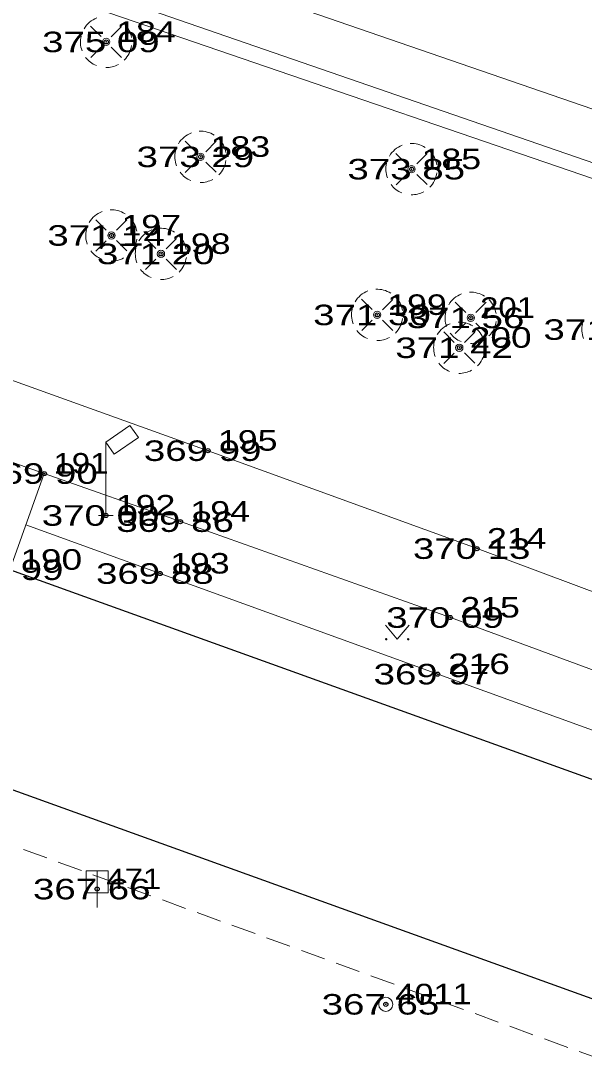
# Model space of a CAD drawing. Extents: x -789669 to -789458, y -977587 to -977420.
# Drawn here: x -789569.11 to -789549.89, y -977497.54 to -977462.39 of the extents above; entities that cross this region are included whole.
import ezdxf
from ezdxf.enums import TextEntityAlignment as Align

# ---------------------------------------------------------------- set-up
doc = ezdxf.new("R2010")
doc.units = 0
doc.header["$LTSCALE"] = 0.28
doc.header["$PDMODE"] = 32
doc.header["$PDSIZE"] = 0.14
doc.linetypes.add('MEDIUM_DASHED', pattern=[4.5, 3, -1.5])
for name, color, linetype, lineweight in [('1', 7, 'Continuous', 13), ('25', 7, 'Continuous', 13), ('3', 7, 'Continuous', 13), ('33', 7, 'Continuous', 13), ('4', 7, 'Continuous', 13), ('50', 7, 'Continuous', 13), ('9', 7, 'Continuous', 25)]:
    doc.layers.add(name, color=color, linetype=linetype, lineweight=lineweight)
for name, color, linetype in [('57', 7, 'Continuous'), ('58', 7, 'Continuous'), ('59', 7, 'Continuous')]:
    doc.layers.add(name, color=color, linetype=linetype)

msp = doc.modelspace()

# ---------------------------------------------------------------- linework, layer by layer
at = {"layer": '1'}
for p, q in [((-789568.3, -977477.84), (-789569.47, -977481.12)), ((-789542.996, -977488.992), (-789568.925, -977479.592))]:
    msp.add_line(p, q, dxfattribs=at)
for points in [[(-789509.64, -977479.12), (-789526.32, -977473.4), (-789544.78, -977467.07), (-789566.2, -977459.68), (-789586.28, -977452.77), (-789604.78, -977446.41), (-789630.61, -977437.53), (-789654.9, -977429.37)], [(-789604.26, -977448.38), (-789586.79, -977454.41), (-789566.59, -977461.37), (-789545.35, -977468.71), (-789526.33, -977475.15), (-789510.21, -977480.66), (-789489.34, -977487.73), (-789463.94, -977496.44)], [(-789591.43, -977469.4), (-789579.77, -977473.66), (-789573.29, -977476.09), (-789568.3, -977477.84), (-789563.66, -977479.48), (-789554.46, -977482.75), (-789542.34, -977487.22), (-789543.54, -977490.46)], [(-789528.28, -977489.67), (-789537.88, -977485.96), (-789544.73, -977483.69), (-789553.55, -977480.4), (-789562.72, -977477.06), (-789579.25, -977471.12)]]:
    msp.add_lwpolyline(points, dxfattribs=at)
at = {"layer": '25'}
msp.add_lwpolyline([(-789566.5, -977492.635), (-789566.5, -977491.385), (-789566.125, -977491.385), (-789566.125, -977492.135), (-789566.875, -977492.135), (-789566.875, -977491.385), (-789566.5, -977491.385)], dxfattribs=at)
at = {"layer": '3'}
msp.add_lwpolyline([(-789601.84, -977457.06), (-789598.55, -977450.95), (-789566.5, -977461.99), (-789545.47, -977469.2), (-789526.54, -977475.63), (-789520.95, -977477.5)], dxfattribs=at)
at = {"layer": '33'}
for p, q in [((-789566.2, -977476.77), (-789566.2, -977479.27)), ((-789566.45, -977479.27), (-789565.95, -977479.27))]:
    msp.add_line(p, q, dxfattribs=at)
msp.add_lwpolyline([(-789566.2, -977476.77), (-789565.38, -977476.197), (-789565.094, -977476.607), (-789565.914, -977477.18)], close=True, dxfattribs=at)
at = {"layer": '4'}
for p, q in [((-789566.724, -977462.582), (-789566.367, -977462.938)), ((-789565.664, -977462.59), (-789566.017, -977462.943)), ((-789566.72, -977463.653), (-789566.368, -977463.302)), ((-789566.19, -977463.126), (-789566.19, -977463.114)), ((-789566.016, -977463.297), (-789565.664, -977463.647)), ((-789563.504, -977466.502), (-789563.147, -977466.858)), ((-789562.444, -977466.51), (-789562.797, -977466.863)), ((-789563.5, -977467.573), (-789563.148, -977467.222)), ((-789562.97, -977467.046), (-789562.97, -977467.034)), ((-789562.796, -977467.217), (-789562.444, -977467.567)), ((-789556.314, -977466.922), (-789555.957, -977467.278)), ((-789555.254, -977466.93), (-789555.607, -977467.283)), ((-789555.78, -977467.466), (-789555.78, -977467.454)), ((-789556.31, -977467.993), (-789555.958, -977467.642)), ((-789555.606, -977467.637), (-789555.254, -977467.987)), ((-789566.544, -977469.182), (-789566.187, -977469.538)), ((-789565.484, -977469.19), (-789565.837, -977469.543)), ((-789566.01, -977469.726), (-789566.01, -977469.714)), ((-789566.54, -977470.253), (-789566.188, -977469.902)), ((-789565.836, -977469.897), (-789565.484, -977470.247)), ((-789564.854, -977469.812), (-789564.497, -977470.168)), ((-789563.794, -977469.82), (-789564.147, -977470.173)), ((-789564.32, -977470.356), (-789564.32, -977470.344)), ((-789564.85, -977470.883), (-789564.498, -977470.532)), ((-789564.146, -977470.527), (-789563.794, -977470.877)), ((-789557.484, -977471.892), (-789557.127, -977472.248)), ((-789556.424, -977471.9), (-789556.777, -977472.253)), ((-789554.294, -977471.992), (-789553.937, -977472.348)), ((-789553.234, -977472), (-789553.587, -977472.353)), ((-789556.95, -977472.436), (-789556.95, -977472.424)), ((-789553.76, -977472.536), (-789553.76, -977472.524)), ((-789557.48, -977472.963), (-789557.128, -977472.612)), ((-789556.776, -977472.607), (-789556.424, -977472.957)), ((-789554.29, -977473.063), (-789553.938, -977472.712)), ((-789553.586, -977472.707), (-789553.234, -977473.057)), ((-789554.684, -977473.012), (-789554.327, -977473.368)), ((-789553.624, -977473.02), (-789553.977, -977473.373)), ((-789554.15, -977473.556), (-789554.15, -977473.544)), ((-789554.68, -977474.083), (-789554.328, -977473.732)), ((-789553.976, -977473.727), (-789553.624, -977474.077))]:
    msp.add_line(p, q, dxfattribs=at)
for points in [[(-789556.672, -977483.011), (-789556.27, -977483.49), (-789555.868, -977483.011)], [(-789556.644, -977483.467), (-789556.63, -977483.475), (-789556.625, -977483.49), (-789556.631, -977483.503), (-789556.644, -977483.511), (-789556.66, -977483.503), (-789556.666, -977483.49), (-789556.662, -977483.476), (-789556.651, -977483.47), (-789556.636, -977483.476), (-789556.631, -977483.49), (-789556.634, -977483.5), (-789556.644, -977483.505), (-789556.655, -977483.5), (-789556.661, -977483.489), (-789556.656, -977483.479), (-789556.651, -977483.476), (-789556.64, -977483.48), (-789556.635, -977483.49), (-789556.641, -977483.497), (-789556.649, -977483.495), (-789556.654, -977483.487), (-789556.649, -977483.482), (-789556.641, -977483.486), (-789556.644, -977483.49)], [(-789555.894, -977483.468), (-789555.88, -977483.476), (-789555.875, -977483.491), (-789555.881, -977483.504), (-789555.894, -977483.512), (-789555.91, -977483.504), (-789555.916, -977483.491), (-789555.912, -977483.477), (-789555.901, -977483.471), (-789555.886, -977483.477), (-789555.881, -977483.491), (-789555.884, -977483.501), (-789555.894, -977483.506), (-789555.905, -977483.501), (-789555.911, -977483.49), (-789555.906, -977483.48), (-789555.901, -977483.477), (-789555.89, -977483.481), (-789555.885, -977483.491), (-789555.891, -977483.498), (-789555.899, -977483.496), (-789555.904, -977483.488), (-789555.899, -977483.483), (-789555.891, -977483.487), (-789555.894, -977483.491)]]:
    msp.add_lwpolyline(points, dxfattribs=at)
for centre, radius in [((-789566.1939, -977463.1194), 0.125), ((-789562.9739, -977467.0394), 0.125), ((-789555.7839, -977467.4594), 0.125), ((-789566.0139, -977469.7194), 0.125), ((-789564.3239, -977470.3494), 0.125), ((-789556.9539, -977472.4294), 0.125), ((-789553.7639, -977472.5294), 0.125), ((-789554.1539, -977473.5494), 0.125), ((-789556.6452, -977483.4897), 0.025), ((-789555.8952, -977483.4897), 0.025)]:
    msp.add_circle(centre, radius, dxfattribs=at)
for centre, start, end in [((-789566.1939, -977463.1194), 111.04924, 149.34666), ((-789566.1939, -977463.1194), 9.68453, 44.47714), ((-789566.1939, -977463.1194), 166.76695, 200.11735), ((-789566.1939, -977463.1194), 315.09105, 351.67435), ((-789566.1939, -977463.1194), 217.06959, 247.69959), ((-789566.1939, -977463.1194), 269.18965, 298.56841), ((-789562.9739, -977467.0394), 57.94289, 92.85253), ((-789562.9739, -977467.0394), 111.04924, 149.34666), ((-789562.9739, -977467.0394), 9.68453, 44.47714), ((-789562.9739, -977467.0394), 166.76695, 200.11735), ((-789555.7839, -977467.4594), 111.04924, 149.34666), ((-789555.7839, -977467.4594), 57.94289, 92.85253), ((-789555.7839, -977467.4594), 9.68453, 44.47714), ((-789562.9739, -977467.0394), 315.09105, 351.67435), ((-789562.9739, -977467.0394), 217.06959, 247.69959), ((-789555.7839, -977467.4594), 166.76695, 200.11735), ((-789555.7839, -977467.4594), 315.09105, 351.67435), ((-789562.9739, -977467.0394), 269.18965, 298.56841), ((-789555.7839, -977467.4594), 217.06959, 247.69959), ((-789555.7839, -977467.4594), 269.18965, 298.56841), ((-789566.0139, -977469.7194), 111.04924, 149.34666), ((-789566.0139, -977469.7194), 57.94289, 92.85253), ((-789566.0139, -977469.7194), 9.68453, 44.47714), ((-789566.0139, -977469.7194), 166.76695, 200.11735), ((-789564.3239, -977470.3494), 111.04924, 149.34666), ((-789564.3239, -977470.3494), 57.94289, 92.85253), ((-789566.0139, -977469.7194), 315.09105, 351.67435), ((-789564.3239, -977470.3494), 9.68453, 44.47714), ((-789566.0139, -977469.7194), 217.06959, 247.69959), ((-789564.3239, -977470.3494), 166.76695, 200.11735), ((-789566.0139, -977469.7194), 269.18965, 298.56841), ((-789564.3239, -977470.3494), 315.09105, 351.67435), ((-789564.3239, -977470.3494), 217.06959, 247.69959), ((-789564.3239, -977470.3494), 269.18965, 298.56841), ((-789556.9539, -977472.4294), 111.04924, 149.34666), ((-789556.9539, -977472.4294), 57.94289, 92.85253), ((-789556.9539, -977472.4294), 9.68453, 44.47714), ((-789553.7639, -977472.5294), 111.04924, 149.34666), ((-789553.7639, -977472.5294), 57.94289, 92.85253), ((-789553.7639, -977472.5294), 9.68453, 44.47714), ((-789556.9539, -977472.4294), 166.76695, 200.11735), ((-789553.7639, -977472.5294), 166.76695, 200.11735), ((-789556.9539, -977472.4294), 315.09105, 351.67435), ((-789554.1539, -977473.5494), 111.04924, 149.34666), ((-789554.1539, -977473.5494), 57.94289, 92.85253), ((-789553.7639, -977472.5294), 315.09105, 351.67435), ((-789549.1039, -977472.9294), 166.76695, 200.11735), ((-789556.9539, -977472.4294), 217.06959, 247.69959), ((-789556.9539, -977472.4294), 269.18965, 298.56841), ((-789553.7639, -977472.5294), 217.06959, 247.69959), ((-789554.1539, -977473.5494), 9.68453, 44.47714), ((-789554.1539, -977473.5494), 166.76695, 200.11735), ((-789553.7639, -977472.5294), 269.18965, 298.56841), ((-789554.1539, -977473.5494), 315.09105, 351.67435), ((-789554.1539, -977473.5494), 217.06959, 247.69959), ((-789554.1539, -977473.5494), 269.18965, 298.56841)]:
    msp.add_arc(centre, 0.875, start, end, dxfattribs=at)
at = {"layer": '50'}
msp.add_line((-789556.668, -977495.94), (-789556.652, -977495.94), dxfattribs=at)
msp.add_circle((-789556.6598, -977495.9405), 0.24, dxfattribs=at)
at = {"layer": '57'}
for p in [(-789566.19, -977463.12), (-789562.97, -977467.04), (-789555.78, -977467.46), (-789566.01, -977469.72), (-789564.32, -977470.35), (-789556.95, -977472.43), (-789553.76, -977472.53), (-789554.15, -977473.55), (-789562.72, -977477.06), (-789568.3, -977477.84), (-789566.2, -977479.27), (-789563.66, -977479.48), (-789553.55, -977480.4), (-789564.35, -977481.25), (-789554.46, -977482.75), (-789554.89, -977484.68), (-789566.5, -977492.01), (-789556.66, -977495.94)]:
    msp.add_point(p, dxfattribs=at)
at = {"layer": '9'}
for p, q in [((-789592.9, -977472.67), (-789543.54, -977490.46)), ((-789546.04, -977497.05), (-789596.85, -977478.72))]:
    msp.add_line(p, q, dxfattribs=at)
at = {"layer": '9', "linetype": 'MEDIUM_DASHED', "lineweight": 13}
msp.add_line((-789597.427, -977480.319), (-789543.101, -977500.084), dxfattribs=at)

# ---------------------------------------------------------------- texts
at = {"layer": '50', "width": 1.25}
msp.add_text(' 4011', height=0.7, dxfattribs=at).set_placement((-789556.66, -977495.94))
at = {"layer": '58'}
for s, width, p in [(' 184', 1.3, (-789566.19, -977463.12)), (' 183', 1.3, (-789562.97, -977467.04)), (' 185', 1.3, (-789555.78, -977467.46)), (' 197', 1.3, (-789566.01, -977469.72)), (' 198', 1.3, (-789564.32, -977470.35)), (' 199', 1.3, (-789556.95, -977472.43)), (' 201', 1.2, (-789553.76, -977472.53)), (' 200', 1.35, (-789554.15, -977473.55)), (' 195', 1.3, (-789562.72, -977477.06)), (' 191', 1.2, (-789568.3, -977477.84)), (' 192', 1.3, (-789566.2, -977479.27)), (' 194', 1.3, (-789563.66, -977479.48)), (' 214', 1.3, (-789553.55, -977480.4)), (' 190', 1.35, (-789569.47, -977481.12)), (' 193', 1.3, (-789564.35, -977481.25)), (' 215', 1.3, (-789554.46, -977482.75)), (' 216', 1.35, (-789554.89, -977484.68)), (' 471', 1.2, (-789566.5, -977492.01)), (' 4011', 1.25, (-789556.66, -977495.94))]:
    msp.add_text(s, height=0.7, dxfattribs=dict(at, width=width)).set_placement(p)
at = {"layer": '59', "width": 1.4}
for s, p in [('375 09 ', (-789566.19, -977463.47)), ('373 29 ', (-789562.97, -977467.39)), ('373 85 ', (-789555.78, -977467.81)), ('371 14 ', (-789566.01, -977470.07)), ('371 20 ', (-789564.32, -977470.7)), ('371 30 ', (-789556.95, -977472.78)), ('371 56 ', (-789553.76, -977472.88)), ('371 99 ', (-789549.1, -977473.28)), ('371 42 ', (-789554.15, -977473.9)), ('369 99 ', (-789562.72, -977477.41)), ('369 90 ', (-789568.3, -977478.19)), ('370 00 ', (-789566.2, -977479.62)), ('369 86 ', (-789563.66, -977479.83)), ('370 13 ', (-789553.55, -977480.75)), ('369 99 ', (-789569.47, -977481.47)), ('369 88 ', (-789564.35, -977481.6)), ('370 09 ', (-789554.46, -977483.1)), ('369 97 ', (-789554.89, -977485.03)), ('367 66 ', (-789566.5, -977492.36)), ('367 65 ', (-789556.66, -977496.29))]:
    msp.add_text(s, height=0.7, dxfattribs=at).set_placement(p, align=Align.CENTER)

doc.saveas('drawing.dxf')
